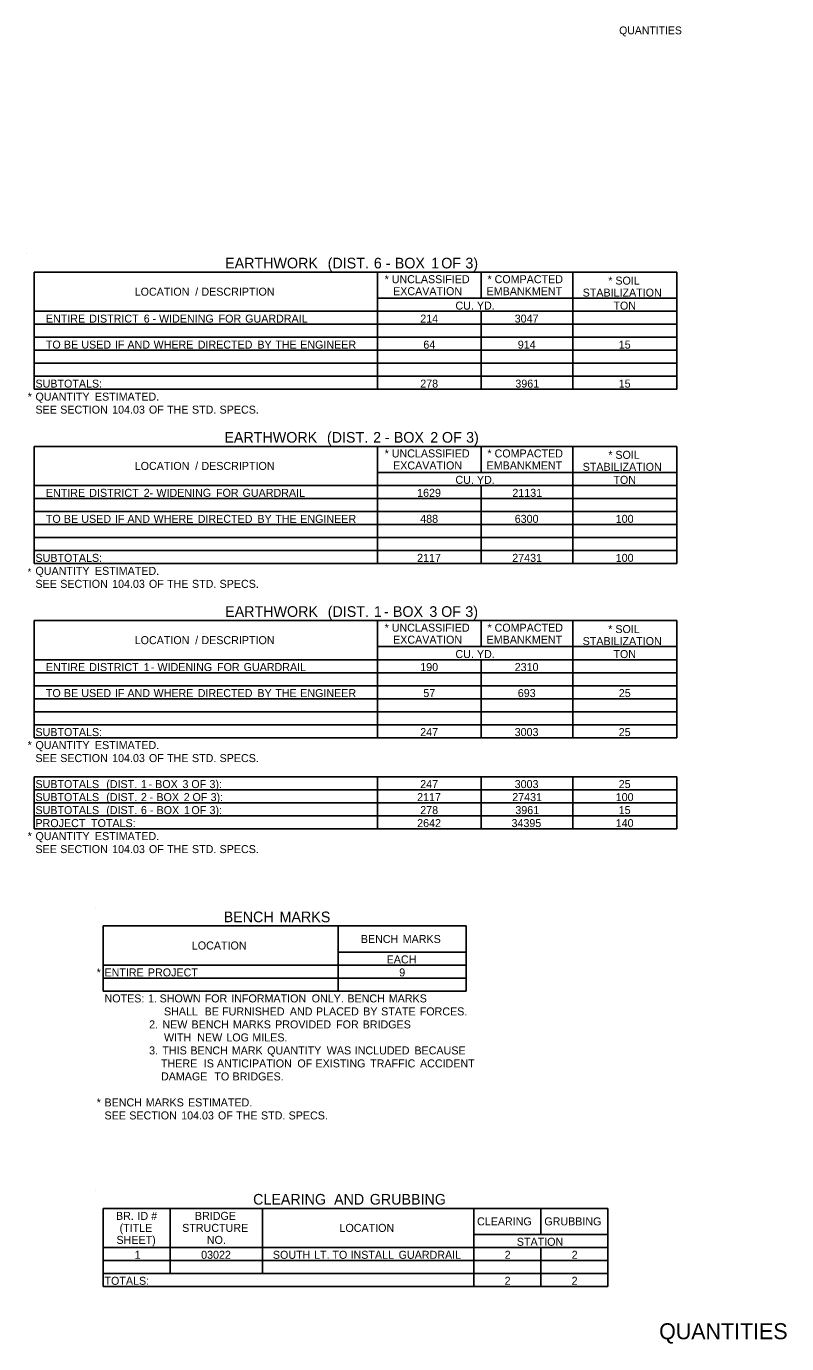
# Model space of a CAD drawing. Extents: x 542596 to 1930787, y -1948294 to 596640.
# Drawn here: x 562319 to 562889, y -1947044 to -1946056 of the extents above; entities that cross this region are included whole.
import ezdxf

# ---------------------------------------------------------------- set-up
doc = ezdxf.new("R2010")
doc.units = 0
for name, color, linetype in [('Default', 7, 'Continuous'), ('R_Border', 7, 'Continuous'), ('R_Border Prem', 7, 'Continuous')]:
    doc.layers.add(name, color=color, linetype=linetype)

msp = doc.modelspace()

# ---------------------------------------------------------------- linework, layer by layer
at = {"layer": 'Default'}
for p, q in [((562318.87, -1946227.15), (562318.87, -1946227.15)), ((562324.72, -1946240.8), (562806.37, -1946240.8)), ((562324.72, -1946318.8), (562324.72, -1946240.8)), ((562324.72, -1946328.55), (562324.72, -1946240.8)), ((562582.12, -1946328.55), (562582.12, -1946240.8)), ((562659.63, -1946260.3), (562659.63, -1946240.8)), ((562728.37, -1946328.55), (562728.37, -1946240.8)), ((562806.37, -1946328.55), (562806.37, -1946240.8)), ((562582.12, -1946260.3), (562806.37, -1946260.3)), ((562324.72, -1946270.05), (562806.37, -1946270.05)), ((562659.63, -1946328.55), (562659.63, -1946270.05)), ((562324.72, -1946279.8), (562806.37, -1946279.8)), ((562324.72, -1946289.55), (562806.37, -1946289.55)), ((562324.72, -1946299.3), (562806.37, -1946299.3)), ((562324.72, -1946309.05), (562806.37, -1946309.05)), ((562324.72, -1946318.8), (562728.37, -1946318.8)), ((562324.72, -1946318.8), (562806.37, -1946318.8)), ((562728.37, -1946318.8), (562806.37, -1946318.8)), ((562324.72, -1946328.55), (562806.37, -1946328.55)), ((562324.72, -1946371.45), (562806.37, -1946371.45)), ((562324.72, -1946449.45), (562324.72, -1946371.45)), ((562324.72, -1946459.2), (562324.72, -1946371.45)), ((562582.12, -1946459.2), (562582.12, -1946371.45)), ((562659.63, -1946390.95), (562659.63, -1946371.45)), ((562728.37, -1946459.2), (562728.37, -1946371.45)), ((562806.37, -1946459.2), (562806.37, -1946371.45)), ((562582.12, -1946390.95), (562806.37, -1946390.95)), ((562324.72, -1946400.7), (562806.37, -1946400.7)), ((562582.12, -1946400.7), (562728.37, -1946400.7)), ((562659.63, -1946459.2), (562659.63, -1946400.7)), ((562324.72, -1946410.45), (562806.37, -1946410.45)), ((562324.72, -1946420.2), (562806.37, -1946420.2)), ((562324.72, -1946429.95), (562806.37, -1946429.95)), ((562324.72, -1946439.7), (562806.37, -1946439.7)), ((562324.72, -1946449.45), (562728.37, -1946449.45)), ((562324.72, -1946449.45), (562806.37, -1946449.45)), ((562728.37, -1946449.45), (562806.37, -1946449.45)), ((562324.72, -1946459.2), (562806.37, -1946459.2)), ((562324.72, -1946502.1), (562806.37, -1946502.1)), ((562324.72, -1946580.1), (562324.72, -1946502.1)), ((562324.72, -1946589.85), (562324.72, -1946502.1)), ((562582.12, -1946589.85), (562582.12, -1946502.1)), ((562659.63, -1946521.6), (562659.63, -1946502.1)), ((562728.37, -1946589.85), (562728.37, -1946502.1)), ((562806.37, -1946589.85), (562806.37, -1946502.1)), ((562582.12, -1946521.6), (562806.37, -1946521.6)), ((562324.72, -1946531.35), (562806.37, -1946531.35)), ((562659.63, -1946589.85), (562659.63, -1946531.35)), ((562324.72, -1946541.1), (562806.37, -1946541.1)), ((562324.72, -1946550.85), (562806.37, -1946550.85)), ((562324.72, -1946560.6), (562806.37, -1946560.6)), ((562324.72, -1946570.35), (562806.37, -1946570.35)), ((562324.72, -1946580.1), (562728.37, -1946580.1)), ((562324.72, -1946580.1), (562806.37, -1946580.1)), ((562728.37, -1946580.1), (562806.37, -1946580.1)), ((562324.72, -1946589.85), (562806.37, -1946589.85)), ((562324.72, -1946619.1), (562806.37, -1946619.1)), ((562324.72, -1946619.1), (562806.37, -1946619.1)), ((562324.72, -1946658.1), (562324.72, -1946619.1)), ((562324.72, -1946658.1), (562324.72, -1946619.1)), ((562582.12, -1946658.1), (562582.12, -1946619.1)), ((562659.63, -1946658.1), (562659.63, -1946619.1)), ((562728.37, -1946658.1), (562728.37, -1946619.1)), ((562806.37, -1946658.1), (562806.37, -1946619.1)), ((562324.72, -1946628.85), (562806.37, -1946628.85)), ((562324.72, -1946638.6), (562806.37, -1946638.6)), ((562324.72, -1946648.35), (562806.37, -1946648.35)), ((562324.72, -1946658.1), (562806.37, -1946658.1)), ((562370.61, -1946717.41), (562370.61, -1946717.41)), ((562376.46, -1946731.06), (562648.48, -1946731.06)), ((562376.46, -1946779.81), (562376.46, -1946731.06)), ((562376.46, -1946779.81), (562376.46, -1946731.06)), ((562552.44, -1946779.81), (562552.44, -1946731.06)), ((562648.48, -1946750.56), (562648.48, -1946731.06)), ((562552.44, -1946750.56), (562648.48, -1946750.56)), ((562648.48, -1946770.06), (562648.48, -1946750.56)), ((562376.46, -1946760.31), (562648.48, -1946760.31)), ((562552.44, -1946779.81), (562552.44, -1946760.31)), ((562376.46, -1946770.06), (562648.48, -1946770.06)), ((562648.48, -1946779.81), (562648.48, -1946770.06)), ((562376.46, -1946779.81), (562648.48, -1946779.81)), ((562370.61, -1946929.16), (562370.61, -1946929.16)), ((562376.46, -1946942.81), (562754.76, -1946942.81)), ((562376.46, -1947001.31), (562376.46, -1946942.81)), ((562376.46, -1947001.31), (562376.46, -1946942.81)), ((562426.67, -1946991.56), (562426.67, -1946942.81)), ((562495.89, -1946991.56), (562495.89, -1946942.81)), ((562654.33, -1947001.31), (562654.33, -1946942.81)), ((562704.54, -1946962.31), (562704.54, -1946942.81)), ((562754.76, -1946972.06), (562754.76, -1946942.81)), ((562654.33, -1946962.31), (562754.76, -1946962.31)), ((562654.33, -1946991.56), (562654.33, -1946962.31)), ((562376.46, -1946972.06), (562754.76, -1946972.06)), ((562426.67, -1946991.56), (562426.67, -1946972.06)), ((562495.89, -1946981.81), (562495.89, -1946972.06)), ((562704.54, -1947001.31), (562704.54, -1946972.06)), ((562704.54, -1947001.31), (562704.54, -1946972.06)), ((562754.76, -1946991.56), (562754.76, -1946972.06)), ((562376.46, -1946981.81), (562754.76, -1946981.81)), ((562376.46, -1946991.56), (562754.76, -1946991.56)), ((562495.89, -1946991.56), (562754.76, -1946991.56)), ((562754.76, -1947001.31), (562754.76, -1946991.56)), ((562376.46, -1947001.31), (562754.76, -1947001.31))]:
    msp.add_line(p, q, dxfattribs=at)

# ---------------------------------------------------------------- texts
for s, height, p in [('EARTHWORK', 8, (562467.84, -1946237.97)), (' (DIST.', 8, (562541.72, -1946237.97)), (' 6', 8, (562576.34, -1946237.97)), (' BOX', 8, (562592.01, -1946237.97)), (' 1', 8, (562619.32, -1946237.97)), (' OF', 8, (562626.83, -1946237.97)), (' 3)', 8, (562644.94, -1946237.97)), (' -', 8, (562585.26, -1946237.97)), (' /', 6, (562443.16, -1946258.42)), ('*', 6, (562587.4, -1946249.05)), (' UNCLASSIFIED', 6, (562590.48, -1946249.05)), ('EXCAVATION', 6, (562593.73, -1946258.05)), ('EMBANKMENT', 6, (562663.81, -1946258.05)), ('*', 6, (562664.49, -1946249.05)), (' COMPACTED', 6, (562667.57, -1946249.05)), ('*', 6, (562755.01, -1946250.1)), (' SOIL', 6, (562758.09, -1946250.1)), ('LOCATION', 6, (562400.06, -1946258.42)), (' DESCRIPTION', 6, (562447.83, -1946258.42)), ('STABILIZATION', 6, (562735.8, -1946259.1)), ('CU.', 6, (562640.45, -1946268.85)), (' YD.', 6, (562654.31, -1946268.85)), ('TON', 6, (562758.86, -1946268.85)), ('ENTIRE', 6, (562333.49, -1946278.6)), (' DISTRICT', 6, (562363.79, -1946278.6)), (' 6', 6, (562404.61, -1946278.6)), (' -', 6, (562411.21, -1946278.6)), (' WIDENING', 6, (562416.07, -1946278.6)), (' FOR', 6, (562460.72, -1946278.6)), (' GUARDRAIL', 6, (562480.63, -1946278.6)), ('214', 6, (562614.09, -1946278.6)), ('3047', 6, (562684.87, -1946278.6)), ('TO', 6, (562333.49, -1946298.1)), (' BE', 6, (562344.76, -1946298.1)), (' USED', 6, (562357.83, -1946298.1)), (' IF', 6, (562383, -1946298.1)), (' AND', 6, (562392.4, -1946298.1)), (' WHERE', 6, (562411.98, -1946298.1)), (' DIRECTED', 6, (562445.07, -1946298.1)), (' BY', 6, (562489.8, -1946298.1)), (' THE', 6, (562503.25, -1946298.1)), (' ENGINEER', 6, (562521.9, -1946298.1)), ('64', 6, (562616.42, -1946298.1)), ('914', 6, (562687.21, -1946298.1)), ('15', 6, (562762.88, -1946298.1)), ('SUBTOTALS:', 6, (562325.69, -1946327.35)), ('278', 6, (562614.07, -1946327.35)), ('3961', 6, (562685.36, -1946327.35)), ('15', 6, (562762.83, -1946327.35)), ('*', 6, (562319.84, -1946337.1)), ('QUANTITY', 6, (562325.69, -1946337.1)), (' ESTIMATED.', 6, (562368.02, -1946337.1)), ('SEE', 6, (562325.69, -1946346.85)), (' SECTION', 6, (562342.02, -1946346.85)), (' 104.03', 6, (562380.93, -1946346.85)), (' OF', 6, (562408.51, -1946346.85)), (' THE', 6, (562422.1, -1946346.85)), (' STD.', 6, (562440.75, -1946346.85)), (' SPECS.', 6, (562461.44, -1946346.85)), ('EARTHWORK', 8, (562467.3, -1946368.62)), (' (DIST.', 8, (562541.18, -1946368.62)), (' 2', 8, (562575.8, -1946368.62)), (' BOX', 8, (562591.3, -1946368.62)), (' 2', 8, (562618.62, -1946368.62)), (' OF', 8, (562627.37, -1946368.62)), (' 3)', 8, (562645.48, -1946368.62)), (' -', 8, (562584.55, -1946368.62)), ('*', 6, (562587.4, -1946379.7)), (' UNCLASSIFIED', 6, (562590.48, -1946379.7)), ('*', 6, (562664.49, -1946379.7)), (' COMPACTED', 6, (562667.57, -1946379.7)), ('*', 6, (562755.01, -1946380.75)), (' SOIL', 6, (562758.09, -1946380.75)), ('LOCATION', 6, (562400.06, -1946389.07)), (' /', 6, (562443.16, -1946389.07)), (' DESCRIPTION', 6, (562447.83, -1946389.07)), ('EXCAVATION', 6, (562593.73, -1946388.7)), ('EMBANKMENT', 6, (562663.81, -1946388.7)), ('STABILIZATION', 6, (562735.8, -1946389.75)), ('CU.', 6, (562640.45, -1946399.5)), (' YD.', 6, (562654.31, -1946399.5)), ('TON', 6, (562758.86, -1946399.5)), ('ENTIRE', 6, (562333.49, -1946409.25)), (' DISTRICT', 6, (562363.79, -1946409.25)), (' 2-', 6, (562404.61, -1946409.25)), (' WIDENING', 6, (562414.12, -1946409.25)), (' FOR', 6, (562458.77, -1946409.25)), (' GUARDRAIL', 6, (562478.68, -1946409.25)), ('1629', 6, (562611.74, -1946409.25)), ('21131', 6, (562683.12, -1946409.25)), ('TO', 6, (562333.49, -1946428.75)), (' BE', 6, (562344.76, -1946428.75)), (' USED', 6, (562357.83, -1946428.75)), (' IF', 6, (562383, -1946428.75)), (' AND', 6, (562392.4, -1946428.75)), (' WHERE', 6, (562411.98, -1946428.75)), (' DIRECTED', 6, (562445.07, -1946428.75)), (' BY', 6, (562489.8, -1946428.75)), (' THE', 6, (562503.25, -1946428.75)), (' ENGINEER', 6, (562521.9, -1946428.75)), ('488', 6, (562614.07, -1946428.75)), ('6300', 6, (562684.88, -1946428.75)), ('100', 6, (562760.58, -1946428.75)), ('SUBTOTALS:', 6, (562325.69, -1946458)), ('2117', 6, (562611.74, -1946458)), ('27431', 6, (562683.03, -1946458)), ('100', 6, (562760.58, -1946458)), ('*', 5, (562319.84, -1946467.95)), ('QUANTITY', 6, (562325.69, -1946467.75)), (' ESTIMATED.', 6, (562368.02, -1946467.75)), ('SEE', 6, (562325.69, -1946477.5)), (' SECTION', 6, (562342.02, -1946477.5)), (' 104.03', 6, (562380.93, -1946477.5)), (' OF', 6, (562408.51, -1946477.5)), (' THE', 6, (562422.1, -1946477.5)), (' STD.', 6, (562440.75, -1946477.5)), (' SPECS.', 6, (562461.44, -1946477.5)), ('EARTHWORK', 8, (562467.88, -1946499.27)), (' (DIST.', 8, (562541.76, -1946499.27)), (' 1', 8, (562576.38, -1946499.27)), (' -', 8, (562583.89, -1946499.27)), (' BOX', 8, (562590.63, -1946499.27)), (' 3', 8, (562617.95, -1946499.27)), (' OF', 8, (562626.79, -1946499.27)), (' 3)', 8, (562644.9, -1946499.27)), ('*', 6, (562587.4, -1946510.35)), (' UNCLASSIFIED', 6, (562590.48, -1946510.35)), ('*', 6, (562664.49, -1946510.35)), (' COMPACTED', 6, (562667.57, -1946510.35)), ('*', 6, (562755.01, -1946511.4)), (' SOIL', 6, (562758.09, -1946511.4)), ('LOCATION', 6, (562400.06, -1946519.72)), (' /', 6, (562443.16, -1946519.72)), (' DESCRIPTION', 6, (562447.83, -1946519.72)), ('EXCAVATION', 6, (562593.73, -1946519.35)), ('EMBANKMENT', 6, (562663.81, -1946519.35)), ('STABILIZATION', 6, (562735.8, -1946520.4)), ('CU.', 6, (562640.45, -1946530.15)), (' YD.', 6, (562654.31, -1946530.15)), ('TON', 6, (562758.86, -1946530.15)), ('ENTIRE', 6, (562333.49, -1946539.9)), (' DISTRICT', 6, (562363.79, -1946539.9)), (' 1', 6, (562404.61, -1946539.9)), (' -', 6, (562410.05, -1946539.9)), (' WIDENING', 6, (562414.91, -1946539.9)), (' FOR', 6, (562459.56, -1946539.9)), (' GUARDRAIL', 6, (562479.47, -1946539.9)), ('190', 6, (562614.09, -1946539.9)), ('2310', 6, (562684.88, -1946539.9)), ('TO', 6, (562333.49, -1946559.4)), (' BE', 6, (562344.76, -1946559.4)), (' USED', 6, (562357.83, -1946559.4)), (' IF', 6, (562383, -1946559.4)), (' AND', 6, (562392.4, -1946559.4)), (' WHERE', 6, (562411.98, -1946559.4)), (' DIRECTED', 6, (562445.07, -1946559.4)), (' BY', 6, (562489.8, -1946559.4)), (' THE', 6, (562503.25, -1946559.4)), (' ENGINEER', 6, (562521.9, -1946559.4)), ('57', 6, (562616.4, -1946559.4)), ('693', 6, (562687.2, -1946559.4)), ('25', 6, (562762.88, -1946559.4)), ('SUBTOTALS:', 6, (562325.69, -1946588.65)), ('247', 6, (562614.07, -1946588.65)), ('3003', 6, (562684.86, -1946588.65)), ('25', 6, (562762.83, -1946588.65)), ('*', 6, (562319.84, -1946598.4)), ('QUANTITY', 6, (562325.69, -1946598.4)), (' ESTIMATED.', 6, (562368.02, -1946598.4)), ('SEE', 6, (562325.69, -1946608.15)), (' SECTION', 6, (562342.02, -1946608.15)), (' 104.03', 6, (562380.93, -1946608.15)), (' OF', 6, (562408.51, -1946608.15)), (' THE', 6, (562422.1, -1946608.15)), (' STD.', 6, (562440.75, -1946608.15)), (' SPECS.', 6, (562461.44, -1946608.15)), ('SUBTOTALS', 6, (562325.69, -1946627.65)), (' (DIST.', 6, (562376.52, -1946627.65)), (' 1', 6, (562402.49, -1946627.65)), (' -', 6, (562408.12, -1946627.65)), (' BOX', 6, (562413.17, -1946627.65)), (' 3', 6, (562433.66, -1946627.65)), (' OF', 6, (562440.29, -1946627.65)), (' 3):', 6, (562453.87, -1946627.65)), ('247', 6, (562614.07, -1946627.65)), ('3003', 6, (562684.86, -1946627.65)), ('25', 6, (562762.83, -1946627.65)), ('SUBTOTALS', 6, (562325.69, -1946637.4)), (' (DIST.', 6, (562376.52, -1946637.4)), (' 2', 6, (562402.49, -1946637.4)), (' -', 6, (562409.05, -1946637.4)), (' BOX', 6, (562414.11, -1946637.4)), (' 2', 6, (562434.6, -1946637.4)), (' OF', 6, (562441.17, -1946637.4)), (' 3):', 6, (562454.75, -1946637.4)), ('2117', 6, (562611.74, -1946637.4)), ('27431', 6, (562683.03, -1946637.4)), ('100', 6, (562760.58, -1946637.4)), ('SUBTOTALS', 6, (562325.69, -1946647.15)), (' (DIST.', 6, (562376.52, -1946647.15)), (' 6', 6, (562402.49, -1946647.15)), (' -', 6, (562409.18, -1946647.15)), (' BOX', 6, (562414.23, -1946647.15)), (' 1', 6, (562434.72, -1946647.15)), (' OF', 6, (562440.35, -1946647.15)), (' 3):', 6, (562453.93, -1946647.15)), ('278', 6, (562614.07, -1946647.15)), ('3961', 6, (562685.36, -1946647.15)), ('15', 6, (562762.83, -1946647.15)), ('PROJECT', 6, (562325.69, -1946656.9)), (' TOTALS:', 6, (562365.12, -1946656.9)), ('2642', 6, (562611.76, -1946656.9)), ('34395', 6, (562682.48, -1946656.9)), ('140', 6, (562760.58, -1946656.9)), ('*', 6, (562319.84, -1946666.65)), ('QUANTITY', 6, (562325.69, -1946666.65)), (' ESTIMATED.', 6, (562368.02, -1946666.65)), ('SEE', 6, (562325.69, -1946676.4)), (' SECTION', 6, (562342.02, -1946676.4)), (' 104.03', 6, (562380.93, -1946676.4)), (' OF', 6, (562408.51, -1946676.4)), (' THE', 6, (562422.1, -1946676.4)), (' STD.', 6, (562440.75, -1946676.4)), (' SPECS.', 6, (562461.44, -1946676.4)), ('BENCH', 8, (562466.78, -1946728.24)), (' MARKS', 8, (562505.67, -1946728.24)), ('LOCATION', 6, (562442.9, -1946748.69)), ('BENCH', 6, (562569.55, -1946743.81)), (' MARKS', 6, (562598.72, -1946743.81)), ('EACH', 6, (562588.91, -1946759.11)), ('*', 6, (562371.58, -1946768.86)), ('ENTIRE', 6, (562377.43, -1946768.86)), (' PROJECT', 6, (562407.73, -1946768.86)), ('9', 6, (562598.33, -1946768.86)), ('NOTES:', 6, (562377.43, -1946788.36)), (' 1.', 6, (562407.91, -1946788.36)), (' SHOWN', 6, (562416.5, -1946788.36)), (' FOR', 6, (562450.27, -1946788.36)), (' INFORMATION', 6, (562470.19, -1946788.36)), (' ONLY.', 6, (562530.51, -1946788.36)), (' BENCH', 6, (562557.26, -1946788.36)), (' MARKS', 6, (562588.26, -1946788.36)), ('                    SHALL', 6, (562377.43, -1946798.11)), (' BE', 6, (562450.25, -1946798.11)), (' FURNISHED', 6, (562463.32, -1946798.11)), (' AND', 6, (562514.11, -1946798.11)), (' PLACED', 6, (562533.69, -1946798.11)), (' BY', 6, (562569.12, -1946798.11)), (' STATE', 6, (562582.57, -1946798.11)), (' FORCES.', 6, (562611.47, -1946798.11)), ('               2.', 6, (562377.43, -1946807.86)), (' NEW', 6, (562418.6, -1946807.86)), (' BENCH', 6, (562440.4, -1946807.86)), (' MARKS', 6, (562471.4, -1946807.86)), (' PROVIDED', 6, (562503.1, -1946807.86)), (' FOR', 6, (562548.78, -1946807.86)), (' BRIDGES', 6, (562568.69, -1946807.86)), ('                    WITH', 6, (562377.43, -1946817.61)), (' NEW', 6, (562444.73, -1946817.61)), (' LOG', 6, (562466.52, -1946817.61)), (' MILES.', 6, (562486.02, -1946817.61)), ('               3.', 6, (562377.43, -1946827.36)), (' THIS', 6, (562418.6, -1946827.36)), (' BENCH', 6, (562439.59, -1946827.36)), (' MARK', 6, (562470.59, -1946827.36)), (' QUANTITY', 6, (562497.13, -1946827.36)), (' WAS', 6, (562541.78, -1946827.36)), (' INCLUDED', 6, (562562.76, -1946827.36)), (' BECAUSE', 6, (562607.5, -1946827.36)), ('                   THERE', 6, (562377.43, -1946837.11)), (' IS', 6, (562449.63, -1946837.11)), (' ANTICIPATION', 6, (562459.44, -1946837.11)), (' OF', 6, (562519.77, -1946837.11)), (' EXISTING', 6, (562533.36, -1946837.11)), (' TRAFFIC', 6, (562574.29, -1946837.11)), (' ACCIDENT', 6, (562611.68, -1946837.11)), ('                   DAMAGE', 6, (562377.43, -1946846.86)), (' TO', 6, (562457.55, -1946846.86)), (' BRIDGES.', 6, (562471.15, -1946846.86)), ('*', 6, (562371.58, -1946866.36)), ('BENCH', 6, (562377.43, -1946866.36)), (' MARKS', 6, (562406.11, -1946866.36)), (' ESTIMATED.', 6, (562437.81, -1946866.36)), ('SEE', 6, (562377.43, -1946876.11)), (' SECTION', 6, (562393.76, -1946876.11)), (' 104.03', 6, (562432.67, -1946876.11)), (' OF', 6, (562460.25, -1946876.11)), (' THE', 6, (562473.83, -1946876.11)), (' STD.', 6, (562492.48, -1946876.11)), (' SPECS.', 6, (562513.18, -1946876.11)), ('CLEARING', 8, (562488.8, -1946939.99)), (' AND', 8, (562546.51, -1946939.99)), (' GRUBBING', 8, (562573.27, -1946939.99)), ('BR.', 6, (562386.04, -1946951.44)), (' ID', 6, (562399.9, -1946951.44)), (' #', 6, (562410.2, -1946951.44)), ('BRIDGE', 6, (562445.19, -1946951.44)), ('CLEARING', 6, (562656.64, -1946955.56)), ('GRUBBING', 6, (562707.08, -1946955.56)), ('SHEET)', 6, (562386.41, -1946969.44)), ('(TITLE', 6, (562388.73, -1946960.44)), ('STRUCTURE', 6, (562435.64, -1946960.44)), ('NO.', 6, (562454.12, -1946969.44)), ('LOCATION', 6, (562553.56, -1946960.44)), ('STATION', 6, (562686.48, -1946970.86)), ('1', 6, (562400, -1946980.61)), ('03022', 6, (562449.85, -1946980.61)), ('SOUTH', 6, (562503.63, -1946980.61)), (' LT.', 6, (562532.3, -1946980.61)), (' TO', 6, (562546.01, -1946980.61)), (' INSTALL', 6, (562559.61, -1946980.61)), (' GUARDRAIL', 6, (562595.65, -1946980.61)), ('2', 6, (562677.33, -1946980.61)), ('2', 6, (562727.54, -1946980.61)), ('TOTALS:', 6, (562377.43, -1947000.11)), ('2', 6, (562677.32, -1947000.11)), ('2', 6, (562727.53, -1947000.11))]:
    msp.add_text(s, height=height, dxfattribs=at).set_placement(p)
at = {"layer": 'R_Border'}
msp.add_text('QUANTITIES', height=12, rotation=360, dxfattribs=at).set_placement((562793.13, -1947040.95))
at = {"layer": 'R_Border Prem'}
msp.add_text('QUANTITIES', height=5.862, rotation=360, dxfattribs=at).set_placement((562763.15, -1946062.39))

doc.saveas('drawing.dxf')
